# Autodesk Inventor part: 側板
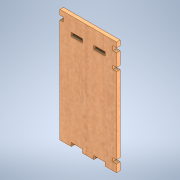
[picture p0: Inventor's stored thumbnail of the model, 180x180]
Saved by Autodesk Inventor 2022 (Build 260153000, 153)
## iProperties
Created: 2024-11
Part Number: 側板
Material: MDF 中密度繊維ボード
Document SubType Name: Modeling
Designer: shimizu
Density: 0.8 g/cm^3
Appearance: サクラ材 - ナチュラル 抑えた光沢
Author: shimizu
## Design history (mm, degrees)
sketch "スケッチ1"
  geometry: L1 (-20.243, 58.107)-(19.757, 58.107); L2 (-4.243, -21.893)-(-4.243, -19.393); L3 (-4.243, -19.393)-(-12.243, -19.393); L4 (-12.243, -19.393)-(-12.243, -21.893); L5 (11.757, -21.893)-(11.757, -19.393); L6 (11.757, -19.393)-(3.757, -19.393); L7 (3.757, -19.393)-(3.757, -21.893); L8 (-12.243, 48.107)-(-4.243, 48.107); L9 (-4.243, 48.107)-(-4.243, 45.607); L10 (-4.243, 45.607)-(-12.243, 45.607); L11 (-12.243, 45.607)-(-12.243, 48.107); L12 (3.757, 48.107)-(11.757, 48.107); L13 (11.757, 48.107)-(11.757, 45.607); L14 (11.757, 45.607)-(3.757, 45.607); L15 (3.757, 45.607)-(3.757, 48.107); L16 (-12.243, -21.893)-(-20.243, -21.893); L17 (19.757, -21.893)-(11.757, -21.893); L18 (3.757, -21.893)-(-4.243, -21.893); L19 (-20.243, 54.607)-(-17.743, 54.607); L20 (-17.743, 54.607)-(-17.743, 51.607); L21 (-17.743, 51.607)-(-20.243, 51.607); L22 (19.757, 54.607)-(17.257, 54.607); L23 (17.257, 54.607)-(17.257, 51.607); L24 (17.257, 51.607)-(19.757, 51.607); L25 (-20.243, -21.893)-(-20.243, 51.607); L26 (-20.243, 54.607)-(-20.243, 58.107); L27 (19.757, 58.107)-(19.757, 54.607); L28 (19.757, 51.607)-(19.757, -21.893); L29 (19.757, 42.607)-(17.257, 42.607); L30 (17.257, 42.607)-(17.257, 40.107); L31 (17.257, 40.107)-(19.757, 40.107); L32 (19.757, 40.107)-(19.757, 42.607); L33 (-20.243, -13.712)-(-17.743, -13.712); L34 (-17.743, -13.712)-(-17.743, -16.212); L35 (-17.743, -16.212)-(-20.243, -16.212); L36 (-20.243, -16.212)-(-20.243, -13.712); L37 (19.757, -13.893)-(17.257, -13.893); L38 (17.257, -13.893)-(17.257, -16.393); L39 (17.257, -16.393)-(19.757, -16.393); L40 (19.757, -16.393)-(19.757, -13.893); 4 further points
  constraints: 80 end point, 21 parallel, 9 perpendicular, 8 horizontal, 3 point on line, 2 collinear
  dimensions: "d27" = 80 distance between parallel lines of L17 L1; "d28" = 40 distance between parallel lines of L25 L28; "d29" = 3 distance between parallel lines of L29 L14; "d30" = 2.5 distance of L30.end L31.end; "d31" = 2.5 distance between parallel lines of L16 L3; "d32" = 3.181 distance between parallel lines of L3 L35; "d33" = 2.5 distance of L33.end L34.end; "d34" = 2.5 distance between parallel lines of L36 L34; "d35" = 2.5 distance between parallel lines of L29 L31; "d37" = 2.5 distance of L37.start L37.end; "d38" = 2.5 distance of L37.end L38.end; "d39" = 2.5 distance of L5.start L5.end; "d40" = 3 distance between parallel lines of L6 L39; "d41" = 3 distance between parallel lines of L24 L22; "d42" = 3.5 distance between parallel lines of L19 L1; "d43" = 3.5 distance between parallel lines of L22 L1; "d44" = 3 distance between parallel lines of L21 L19
extrude "押し出し1" new body sketch "スケッチ1" distance "d13" = 2.5; taper "d14" = 0 deg
node "ソリッド1"
